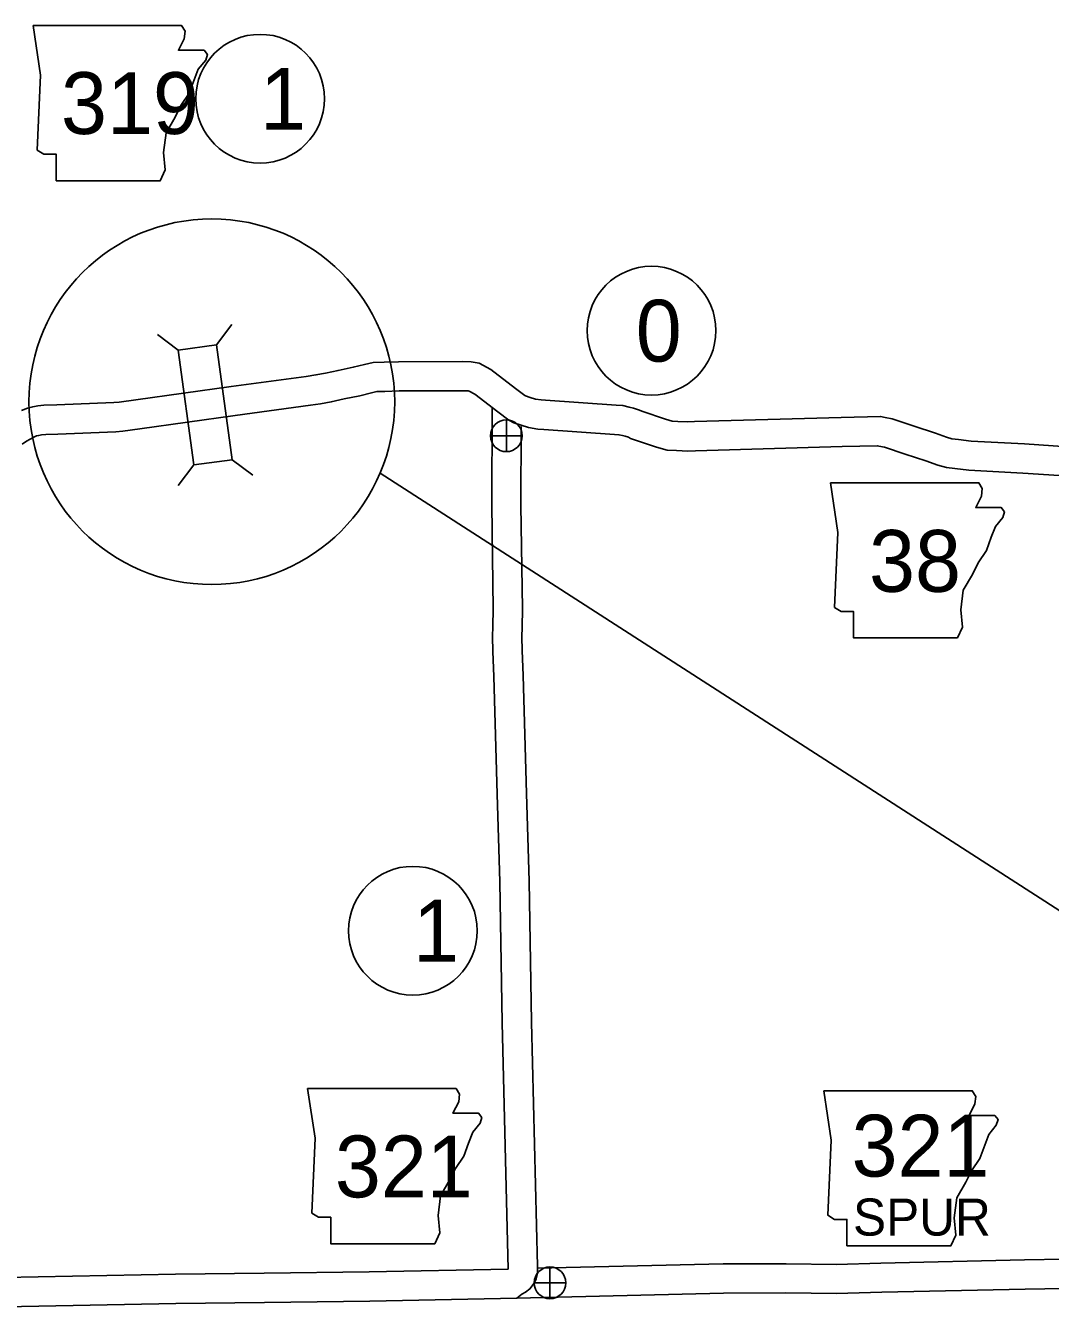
# Model space of a CAD drawing. Extents: x 1367863 to 1368197, y 380048 to 380261.
# Drawn here: x 1367905.41 to 1367923.7, y 380206.32 to 380229.13 of the extents above; entities that cross this region are included whole.
import ezdxf

# ---------------------------------------------------------------- set-up
doc = ezdxf.new("R2010")
doc.units = 0
for name, color, linetype in [('Level 10', 7, 'Continuous'), ('Level 20', 7, 'Continuous'), ('Level 21', 7, 'Continuous'), ('Level 26', 7, 'Continuous'), ('Level 27', 7, 'Continuous'), ('R_Border', 7, 'Continuous'), ('R_Dimension', 7, 'Continuous')]:
    doc.layers.add(name, color=color, linetype=linetype)

msp = doc.modelspace()

# ---------------------------------------------------------------- linework, layer by layer
at = {"layer": 'Level 10'}
for points in [[(1367905.338, 380222.259), (1367905.442, 380222.3), (1367905.539, 380222.325), (1367905.628, 380222.339), (1367905.736, 380222.35), (1367905.968, 380222.357), (1367906.984, 380222.398), (1367907.081, 380222.407), (1367907.376, 380222.45), (1367909.08, 380222.684), (1367910.419, 380222.867), (1367910.59, 380222.894), (1367910.762, 380222.924), (1367910.986, 380222.973), (1367911.257, 380223.03), (1367911.46, 380223.08), (1367911.613, 380223.115), (1367911.808, 380223.119), (1367912.065, 380223.128), (1367913.204, 380223.131), (1367913.361, 380223.129), (1367913.507, 380223.1), (1367913.712, 380222.987), (1367914.154, 380222.651), (1367914.317, 380222.527), (1367914.331, 380222.519), (1367914.415, 380222.491), (1367914.508, 380222.462), (1367914.608, 380222.446), (1367914.691, 380222.442), (1367915.952, 380222.351), (1367916.067, 380222.344), (1367916.183, 380222.32), (1367916.26, 380222.299), (1367916.368, 380222.263), (1367916.407, 380222.243), (1367916.829, 380222.103), (1367916.95, 380222.067), (1367917.047, 380222.063), (1367917.23, 380222.055), (1367917.347, 380222.059), (1367919.966, 380222.135), (1367920.668, 380222.152), (1367920.752, 380222.133), (1367920.873, 380222.106), (1367921.269, 380221.977), (1367921.65, 380221.852), (1367921.846, 380221.779), (1367921.942, 380221.754), (1367922.057, 380221.739), (1367922.286, 380221.711), (1367923.236, 380221.662), (1367924.261, 380221.594)], [(1367905.349, 380221.658), (1367905.425, 380221.712), (1367905.492, 380221.749), (1367905.557, 380221.784), (1367905.604, 380221.803), (1367905.645, 380221.813), (1367905.695, 380221.821), (1367905.771, 380221.829), (1367905.986, 380221.835), (1367907.018, 380221.877), (1367907.143, 380221.888), (1367907.45, 380221.933), (1367909.151, 380222.166), (1367910.495, 380222.35), (1367910.676, 380222.378), (1367910.864, 380222.411), (1367911.096, 380222.463), (1367911.374, 380222.52), (1367911.581, 380222.572), (1367911.677, 380222.594), (1367911.823, 380222.597), (1367912.075, 380222.606), (1367913.202, 380222.608), (1367913.306, 380222.607), (1367913.325, 380222.604), (1367913.427, 380222.548), (1367913.838, 380222.236), (1367914.034, 380222.085), (1367914.126, 380222.037), (1367914.256, 380221.994), (1367914.387, 380221.953), (1367914.553, 380221.925), (1367914.661, 380221.921), (1367915.918, 380221.829), (1367915.998, 380221.825), (1367916.061, 380221.812), (1367916.109, 380221.798), (1367916.167, 380221.78), (1367916.205, 380221.76), (1367916.671, 380221.606), (1367916.862, 380221.547), (1367917.026, 380221.541), (1367917.226, 380221.532), (1367917.362, 380221.537), (1367919.98, 380221.613), (1367920.614, 380221.628), (1367920.635, 380221.623), (1367920.735, 380221.601), (1367921.107, 380221.481), (1367921.477, 380221.359), (1367921.688, 380221.281), (1367921.841, 380221.24), (1367921.992, 380221.221), (1367922.24, 380221.19), (1367923.205, 380221.14), (1367924.223, 380221.073)], [(1367913.734, 380222.305), (1367913.728, 380220.566), (1367913.755, 380218.718), (1367913.749, 380218.404), (1367913.742, 380218.221), (1367913.75, 380217.954), (1367913.766, 380217.508), (1367913.825, 380215.407), (1367913.872, 380213.844), (1367913.917, 380211.326), (1367914.023, 380206.934)], [(1367914.255, 380221.974), (1367914.25, 380220.569), (1367914.277, 380218.717), (1367914.271, 380218.389), (1367914.264, 380218.219), (1367914.272, 380217.971), (1367914.288, 380217.525), (1367914.347, 380215.422), (1367914.394, 380213.857), (1367914.439, 380211.337), (1367914.544, 380206.985), (1367914.545, 380206.851), (1367914.523, 380206.76), (1367914.485, 380206.682), (1367914.411, 380206.578), (1367914.334, 380206.521), (1367914.267, 380206.483), (1367914.174, 380206.415)], [(1367914.545, 380206.947), (1367917.856, 380207.027), (1367918.98, 380207.029), (1367919.879, 380207.016), (1367920.674, 380207.04), (1367923.236, 380207.095), (1367925.359, 380207.131), (1367928.281, 380207.157)], [(1367914.023, 380206.934), (1367911.542, 380206.881), (1367909.666, 380206.86), (1367908.084, 380206.839), (1367905.025, 380206.781), (1367902.622, 380206.732), (1367900.509, 380206.697), (1367899.595, 380206.681), (1367898.605, 380206.648), (1367897.541, 380206.629), (1367895.723, 380206.595)], [(1367914.175, 380206.415), (1367917.863, 380206.505), (1367918.977, 380206.507), (1367919.883, 380206.494), (1367920.688, 380206.518), (1367923.246, 380206.573), (1367925.366, 380206.608), (1367928.293, 380206.634)], [(1367914.174, 380206.415), (1367911.551, 380206.359), (1367909.672, 380206.337), (1367908.092, 380206.316), (1367905.035, 380206.258), (1367902.632, 380206.209), (1367900.518, 380206.174), (1367899.608, 380206.159), (1367898.619, 380206.126), (1367897.551, 380206.107), (1367895.732, 380206.073)]]:
    msp.add_lwpolyline(points, dxfattribs=at)
at = {"layer": 'Level 20'}
for p, q in [((1367908.132, 380223.334), (1367907.766, 380223.612)), ((1367908.815, 380223.428), (1367909.093, 380223.794)), ((1367909.097, 380221.379), (1367909.463, 380221.101)), ((1367908.414, 380221.285), (1367908.136, 380220.919))]:
    msp.add_line(p, q, dxfattribs=at)
msp.add_lwpolyline([(1367908.132, 380223.334), (1367908.414, 380221.285), (1367909.097, 380221.379), (1367908.815, 380223.428)], close=True, dxfattribs=at)
at = {"layer": 'Level 21'}
for points in [[(1367905.546, 380229.129), (1367905.679, 380228.245), (1367905.62, 380226.905), (1367905.738, 380226.831), (1367905.958, 380226.831), (1367905.958, 380226.36), (1367907.814, 380226.36), (1367907.903, 380226.551), (1367907.873, 380226.86), (1367907.917, 380227.214), (1367908.079, 380227.494), (1367908.182, 380227.7), (1367908.33, 380227.921), (1367908.418, 380228.157), (1367908.492, 380228.348), (1367908.624, 380228.51), (1367908.654, 380228.613), (1367908.595, 380228.687), (1367908.138, 380228.687), (1367908.241, 380228.893), (1367908.256, 380229.026), (1367908.195, 380229.127)], [(1367919.772, 380220.966), (1367919.905, 380220.082), (1367919.846, 380218.742), (1367919.964, 380218.668), (1367920.185, 380218.668), (1367920.185, 380218.197), (1367922.04, 380218.197), (1367922.129, 380218.388), (1367922.099, 380218.698), (1367922.144, 380219.051), (1367922.306, 380219.331), (1367922.409, 380219.537), (1367922.556, 380219.758), (1367922.644, 380219.994), (1367922.718, 380220.185), (1367922.851, 380220.347), (1367922.88, 380220.45), (1367922.821, 380220.524), (1367922.365, 380220.524), (1367922.468, 380220.73), (1367922.482, 380220.863), (1367922.421, 380220.965)], [(1367910.444, 380210.155), (1367910.577, 380209.272), (1367910.518, 380207.931), (1367910.636, 380207.858), (1367910.857, 380207.858), (1367910.857, 380207.386), (1367912.713, 380207.386), (1367912.801, 380207.578), (1367912.771, 380207.887), (1367912.816, 380208.241), (1367912.978, 380208.52), (1367913.081, 380208.727), (1367913.228, 380208.948), (1367913.316, 380209.183), (1367913.39, 380209.375), (1367913.523, 380209.537), (1367913.552, 380209.64), (1367913.493, 380209.714), (1367913.037, 380209.714), (1367913.14, 380209.92), (1367913.154, 380210.052), (1367913.093, 380210.154)], [(1367919.655, 380210.117), (1367919.787, 380209.233), (1367919.728, 380207.893), (1367919.846, 380207.819), (1367920.067, 380207.819), (1367920.067, 380207.348), (1367921.923, 380207.348), (1367922.011, 380207.54), (1367921.982, 380207.849), (1367922.026, 380208.202), (1367922.188, 380208.482), (1367922.291, 380208.688), (1367922.439, 380208.909), (1367922.527, 380209.145), (1367922.601, 380209.337), (1367922.733, 380209.499), (1367922.763, 380209.602), (1367922.704, 380209.675), (1367922.247, 380209.675), (1367922.35, 380209.882), (1367922.365, 380210.014), (1367922.304, 380210.116)]]:
    msp.add_lwpolyline(points, close=True, dxfattribs=at)
at = {"layer": 'Level 26'}
for p, q in [((1367913.991, 380221.523), (1367913.991, 380222.089)), ((1367913.708, 380221.806), (1367914.274, 380221.806)), ((1367914.768, 380206.404), (1367914.768, 380206.97)), ((1367914.485, 380206.687), (1367915.05, 380206.687))]:
    msp.add_line(p, q, dxfattribs=at)
for centre in [(1367913.991, 380221.806), (1367914.768, 380206.687)]:
    msp.add_circle(centre, 0.283, dxfattribs=at)
at = {"layer": 'Level 27'}
for centre in [(1367909.595, 380227.823), (1367916.58, 380223.683), (1367912.322, 380212.972)]:
    msp.add_circle(centre, 1.149, dxfattribs=at)
at = {"layer": 'R_Border'}
msp.add_line((1367911.738, 380221.14), (1367939.285, 380203.384), dxfattribs=at)
at = {"layer": 'R_Dimension'}
msp.add_circle((1367908.734, 380222.414), 3.263, dxfattribs=at)

# ---------------------------------------------------------------- texts
at = {"layer": 'Level 21'}
for s, height, p in [('319', 1.1032, (1367906.042, 380227.193)), ('38', 1.1032, (1367920.462, 380219.021)), ('321', 1.1032, (1367920.15, 380208.584)), ('321', 1.1032, (1367910.93, 380208.213)), ('SPUR', 0.6619, (1367920.176, 380207.53))]:
    msp.add_text(s, height=height, dxfattribs=at).set_placement(p)
at = {"layer": 'Level 27'}
for s, p in [('1', (1367909.595, 380227.271)), ('0', (1367916.299, 380223.131)), ('1', (1367912.322, 380212.421))]:
    msp.add_text(s, height=1.103, dxfattribs=at).set_placement(p)

doc.saveas('drawing.dxf')
